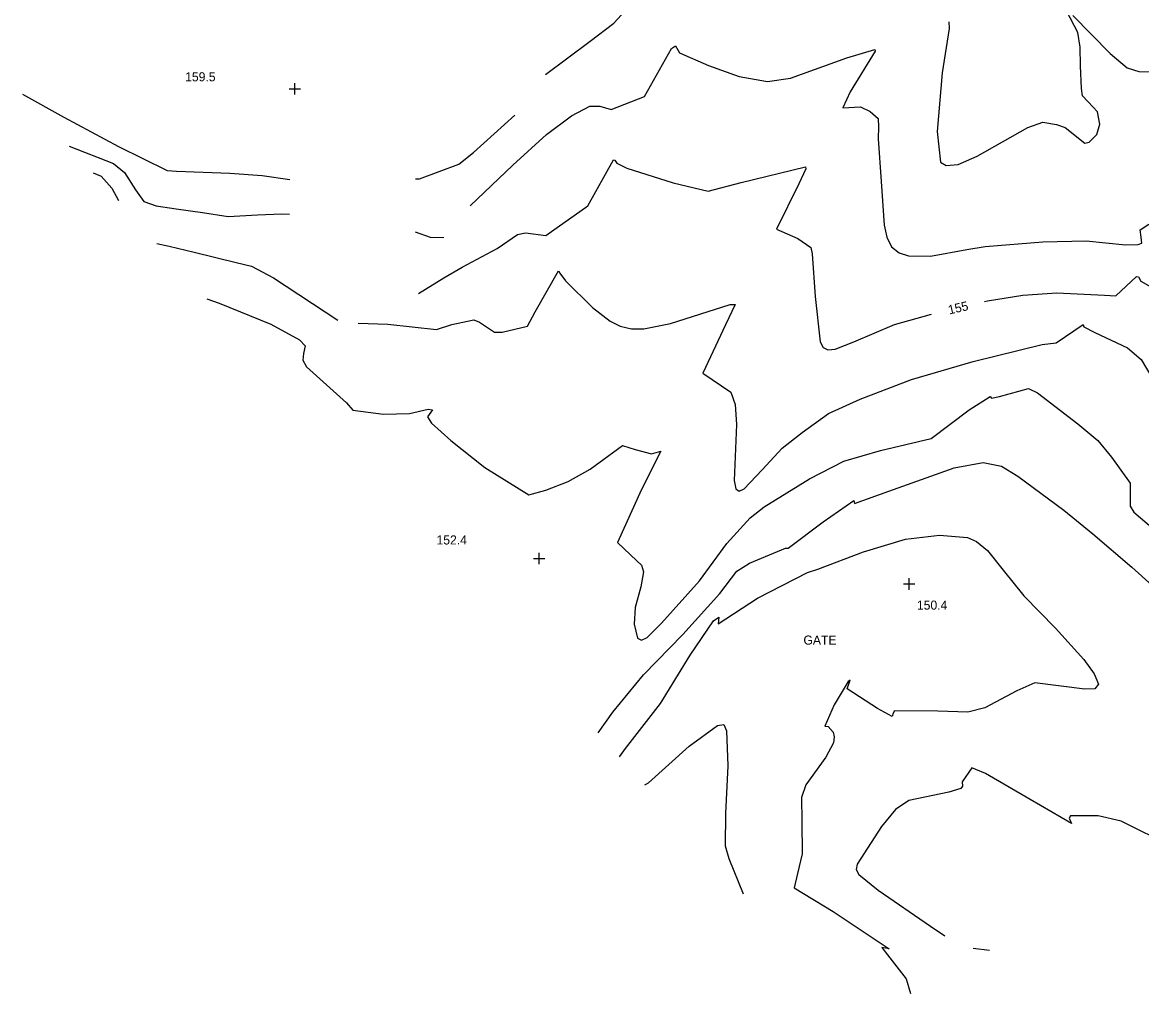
# Model space of a CAD drawing. Extents: x 1467615 to 2003689, y 770235 to 1108726.
# Drawn here: x 2000118.3 to 2000364.7, y 773604.6 to 773818.5 of the extents above; entities that cross this region are included whole.
import ezdxf

# ---------------------------------------------------------------- set-up
doc = ezdxf.new("R2010")
doc.units = 0
for name, color, linetype in [('RD_DTM_Major1', 7, 'Continuous'), ('RD_DTM_Major1_Lbl', 7, 'Continuous'), ('RD_DTM_Minor1', 7, 'Continuous'), ('RD_DTM_Spot_Elev', 7, 'Continuous'), ('RD_TX_Misc1', 7, 'Continuous')]:
    doc.layers.add(name, color=color, linetype=linetype)

msp = doc.modelspace()

# ---------------------------------------------------------------- linework, layer by layer
at = {"layer": 'RD_DTM_Major1'}
for points in [[(2000205.53, 773758.76), (2000211.1, 773762.28), (2000215.13, 773764.63), (2000222.82, 773768.69), (2000227.32, 773771.82), (2000229.05, 773772.15), (2000233.54, 773771.59), (2000242.82, 773778.1), (2000248.44, 773788.26), (2000248.71, 773788.16), (2000249.16, 773787.5), (2000251.37, 773786.37), (2000261.59, 773783.18), (2000269.32, 773781.3), (2000276.59, 773783.21), (2000290.7, 773786.7), (2000290.82, 773786.28), (2000289.22, 773782.93), (2000284.34, 773772.93), (2000289.03, 773770.87), (2000291.9, 773768.9), (2000292.16, 773767.51), (2000292.83, 773758.1), (2000293.94, 773748.12), (2000294.58, 773746.94), (2000295.64, 773746.42), (2000297.22, 773746.56), (2000301.4, 773748.17), (2000310.31, 773751.94), (2000318.45, 773754.27)], [(2000330.13, 773757), (2000330.82, 773757.16), (2000338.57, 773758.45), (2000346.09, 773758.91), (2000356.53, 773758.43), (2000359.08, 773758.27), (2000363.64, 773762.56), (2000364.04, 773762.47), (2000364.58, 773761.51), (2000372.9, 773756.74)], [(2000255.32, 773650.63), (2000256.12, 773651.08), (2000265.13, 773659.11), (2000271.38, 773663.67), (2000272.73, 773663.86), (2000273.3, 773662.49), (2000273.6, 773654.8), (2000273.08, 773644.29), (2000273.01, 773637.19), (2000273.81, 773634.37), (2000276.98, 773626.6)]]:
    msp.add_lwpolyline(points, dxfattribs=at)
at = {"layer": 'RD_DTM_Minor1'}
msp.add_line((2000327.66, 773614.62), (2000331.22, 773614.19), dxfattribs=at)
for points in [[(2000233.45, 773806.99), (2000243.33, 773814.36), (2000248.49, 773818.34), (2000252.77, 773822.97)], [(2000349.6, 773820.04), (2000357.83, 773811.67), (2000361.58, 773808.47), (2000364.13, 773807.71), (2000374.96, 773807.56), (2000379.56, 773807.08), (2000384.73, 773805.98), (2000390.32, 773804.01), (2000396.12, 773801.06), (2000406.8, 773793.9), (2000417.87, 773785.7), (2000419.44, 773785.74), (2000420.3, 773785.42), (2000422.44, 773785.19), (2000423.41, 773785.88), (2000423.53, 773787.69), (2000422.52, 773793.95), (2000421.26, 773796.96), (2000415.59, 773806.54), (2000410.59, 773817.87), (2000408.87, 773823.91)], [(2000322.25, 773818.59), (2000322.35, 773817.13), (2000320.8, 773807.35), (2000319.74, 773794.47), (2000320.42, 773787.75), (2000321.7, 773786.95), (2000324.34, 773787.19), (2000328.54, 773789.02), (2000339.68, 773795.37), (2000342.96, 773796.5), (2000345.97, 773796.04), (2000347.88, 773795.33), (2000352.23, 773791.93), (2000353.2, 773792.15), (2000354.86, 773793.83), (2000355.57, 773796.11), (2000355.06, 773798.82), (2000354.08, 773799.86), (2000351.7, 773802.31), (2000351.5, 773803.94), (2000351.28, 773808.92), (2000351.22, 773813.06), (2000350.7, 773816.24), (2000348.2, 773821.02)], [(2000216.9, 773778.07), (2000226.31, 773787.05), (2000233.66, 773793.79), (2000239.18, 773797.94), (2000243.25, 773800.02), (2000245.43, 773800.04), (2000247.9, 773799.32), (2000255.29, 773802.19), (2000261.24, 773812.76), (2000262.07, 773813.35), (2000262.98, 773811.77), (2000269.36, 773809.01), (2000276.13, 773806.57), (2000282.39, 773805.48), (2000287.42, 773806.24), (2000299.79, 773810.69), (2000306.01, 773812.49), (2000306.07, 773812.17), (2000300.55, 773803.18), (2000298.91, 773799.66), (2000302.81, 773799.9), (2000304.99, 773798.86), (2000306.71, 773797.32), (2000306.79, 773795.52), (2000306.71, 773792.88), (2000307.39, 773783.47), (2000308.02, 773773.85), (2000308.6, 773771.17), (2000309.66, 773769.1), (2000311.32, 773767.78), (2000313.42, 773767.11), (2000318.25, 773767.04), (2000326.24, 773768.45), (2000330.28, 773769.18), (2000343.02, 773770.2), (2000352.5, 773770.36), (2000361.19, 773769.52), (2000363.98, 773769.58), (2000364.76, 773769.89), (2000364.62, 773771.22), (2000364.45, 773772.84), (2000366.35, 773774.07)], [(2000118.28, 773802.71), (2000127.4, 773797.62), (2000139.42, 773791.14), (2000150.18, 773785.85), (2000152.18, 773785.71), (2000163.95, 773785.27), (2000171.08, 773784.75), (2000177.17, 773783.9)], [(2000204.86, 773784.03), (2000205.71, 773784.05), (2000214.37, 773787.28), (2000217.6, 773789.82), (2000226.72, 773798.08)], [(2000128.58, 773791.27), (2000138.37, 773787.41), (2000140.75, 773785.47), (2000143.15, 773781.61), (2000144.99, 773779.05), (2000147.72, 773778.12), (2000152.12, 773777.45), (2000157.95, 773776.62), (2000163.57, 773775.73), (2000170.05, 773776.09), (2000175.39, 773776.32), (2000177.11, 773776.27)], [(2000133.89, 773785.38), (2000135.6, 773784.64), (2000138, 773781.99), (2000139.42, 773779.24)], [(2000204.77, 773772.4), (2000208.07, 773771.18), (2000211.09, 773771.15)], [(2000147.9, 773769.84), (2000150.61, 773769.25), (2000156.12, 773767.89), (2000165.32, 773765.64), (2000168.75, 773764.84), (2000173.57, 773762.23), (2000187.72, 773752.91)], [(2000192.21, 773752.25), (2000198.78, 773752.03), (2000209.46, 773750.84), (2000212.87, 773751.97), (2000217.72, 773753), (2000218.91, 773752.47), (2000222.26, 773750.31), (2000223.95, 773750.27), (2000229.5, 773751.58), (2000231.17, 773754.77), (2000236.33, 773763.81), (2000236.62, 773763.26), (2000237.88, 773761.59), (2000243.85, 773755.69), (2000247.74, 773752.67), (2000249.94, 773751.6), (2000252.4, 773751.02), (2000255.14, 773751.02), (2000261.03, 773752.22), (2000274.13, 773756.34), (2000275.2, 773756.4), (2000273.09, 773751.93), (2000268.15, 773741.24), (2000274.3, 773737.05), (2000275.24, 773734.39), (2000275.52, 773729.94), (2000275.05, 773717.65), (2000275.38, 773715.82), (2000276.14, 773715.28), (2000277.25, 773715.8), (2000281.17, 773719.98), (2000285.6, 773724.73), (2000290.01, 773728.17), (2000295.8, 773732.35), (2000302.74, 773735.56), (2000314.03, 773739.83), (2000327.68, 773743.81), (2000342.87, 773747.54), (2000345.89, 773747.96), (2000351.87, 773751.97), (2000352.02, 773751.44), (2000354.44, 773750.22), (2000361.6, 773746.8), (2000364.61, 773744.27), (2000367.19, 773739.96)], [(2000158.88, 773757.65), (2000161.61, 773756.67), (2000172.96, 773752.02), (2000179.3, 773748.56), (2000180.54, 773747.29), (2000180.19, 773745.62), (2000180.03, 773744.13), (2000180.84, 773742.62), (2000189.63, 773734.7), (2000191.06, 773733.09), (2000197.78, 773732.23), (2000203.49, 773732.34), (2000207.6, 773733.32), (2000208.57, 773733.18), (2000207.45, 773731.66), (2000208.33, 773730.24), (2000212.61, 773726.41), (2000220.14, 773720.51), (2000229.83, 773714.46), (2000233.53, 773715.52), (2000238.44, 773717.4), (2000243.34, 773720.12), (2000250.44, 773725.32), (2000253.25, 773724.45), (2000256.81, 773723.51), (2000258.84, 773724.1), (2000254.63, 773715.63), (2000249.3, 773703.97), (2000253.6, 773699.9), (2000254.61, 773698.99), (2000255.05, 773697.52), (2000254.43, 773694.17), (2000253.21, 773689.67), (2000252.97, 773685.96), (2000253.74, 773682.92), (2000254.63, 773682.46), (2000255.87, 773683.03), (2000259, 773686.18), (2000267.39, 773695.51), (2000273.4, 773703.72), (2000278.52, 773709.43), (2000281.62, 773711.79), (2000291.59, 773718.01), (2000299.2, 773721.86), (2000307.27, 773724.26), (2000318.4, 773726.85), (2000326.79, 773733.18), (2000331.42, 773736.14), (2000331.68, 773735.76), (2000333.44, 773736.14), (2000339.82, 773737.86), (2000341.8, 773736.95), (2000350.66, 773730.1), (2000355.07, 773726.42), (2000358.08, 773722.74), (2000362.21, 773717.03), (2000362.22, 773712), (2000363.06, 773710.65), (2000370.91, 773703.98)], [(2000245.05, 773662.03), (2000248.31, 773666.61), (2000255.05, 773674.8), (2000263.73, 773683.71), (2000271.86, 773692.73), (2000275.59, 773697.62), (2000278.41, 773699.39), (2000286.33, 773702.7), (2000286.88, 773702.7), (2000294.63, 773708.55), (2000301.35, 773713.2), (2000301.55, 773712.55), (2000309.06, 773715.3), (2000323.48, 773720.42), (2000329.85, 773721.59), (2000333.89, 773720.74), (2000337.49, 773718.54), (2000347.63, 773711.1), (2000354, 773705.89), (2000362.62, 773698.57), (2000371.52, 773690.44)], [(2000249.76, 773656.8), (2000251.09, 773658.61), (2000258.8, 773668.55), (2000265.33, 773679.19), (2000270.48, 773686.69), (2000271.65, 773687.51), (2000271.46, 773686.05), (2000280.19, 773691.74), (2000291.17, 773697.34), (2000293.45, 773698.09), (2000303.53, 773701.89), (2000312.76, 773704.67), (2000320.22, 773705.6), (2000326.41, 773705.1), (2000328.41, 773704.19), (2000330.83, 773702.21), (2000334.22, 773697.89), (2000338.78, 773692.24), (2000345.78, 773685.1), (2000351.98, 773678.23), (2000354.29, 773675.08), (2000355.24, 773672.79), (2000354.41, 773671.73), (2000352.26, 773671.64), (2000341.19, 773673.1), (2000337.29, 773671.33), (2000330.24, 773667.53), (2000326.47, 773666.6), (2000319.86, 773666.83), (2000310.35, 773666.93), (2000310.03, 773666.42), (2000309.83, 773665.68), (2000306.59, 773667.38), (2000299.93, 773671.72), (2000300.53, 773673.68), (2000300.15, 773673.36), (2000297.07, 773668.22), (2000294.96, 773663.5), (2000295.73, 773663.45), (2000296.78, 773662.21), (2000297.06, 773661.15), (2000296.92, 773659.84), (2000295.19, 773656.67), (2000290.82, 773650.64), (2000289.87, 773647.81), (2000289.92, 773642.52), (2000289.99, 773635.43), (2000288.99, 773631.1), (2000288.23, 773627.94), (2000296.83, 773622.72), (2000309.17, 773614.48), (2000307.54, 773614.82), (2000308.77, 773613.14), (2000312.92, 773607.91), (2000313.85, 773604.64)], [(2000371.46, 773637.06), (2000360.26, 773642.6), (2000355.17, 773643.78), (2000349.08, 773643.81), (2000348.77, 773643.29), (2000349.29, 773642.08), (2000340.17, 773647.41), (2000330.39, 773653.14), (2000327.38, 773654.37), (2000325.2, 773651.27), (2000325.28, 773650.28), (2000324.96, 773649.8), (2000322.31, 773648.97), (2000313.5, 773647.16), (2000310.53, 773645.21), (2000307.44, 773641.45), (2000302.08, 773633.14), (2000301.86, 773632), (2000302.46, 773630.86), (2000306.7, 773627.41), (2000318.24, 773619.46), (2000321.44, 773617.33)]]:
    msp.add_lwpolyline(points, dxfattribs=at)
at = {"layer": 'RD_DTM_Spot_Elev'}
for p, q in [((2000178.25, 773802.6), (2000178.25, 773805.1)), ((2000177, 773803.85), (2000179.5, 773803.85)), ((2000232.06, 773699.21), (2000232.06, 773701.71)), ((2000230.81, 773700.46), (2000233.31, 773700.46)), ((2000312.33, 773694.83), (2000314.83, 773694.83)), ((2000313.58, 773693.58), (2000313.58, 773696.08))]:
    msp.add_line(p, q, dxfattribs=at)

# ---------------------------------------------------------------- texts
at = {"layer": 'RD_DTM_Major1_Lbl'}
msp.add_text('155', height=2, rotation=13.0597, dxfattribs=at).set_placement((2000322.38, 773754.17))
at = {"layer": 'RD_DTM_Spot_Elev'}
for s, p in [('159.5', (2000154.12, 773805.51)), ('152.4', (2000209.47, 773703.53)), ('150.4', (2000315.26, 773689.18))]:
    msp.add_text(s, height=2, dxfattribs=at).set_placement(p)
at = {"layer": 'RD_TX_Misc1'}
msp.add_text('GATE', height=2, dxfattribs=at).set_placement((2000290.27, 773681.48))

doc.saveas('drawing.dxf')
